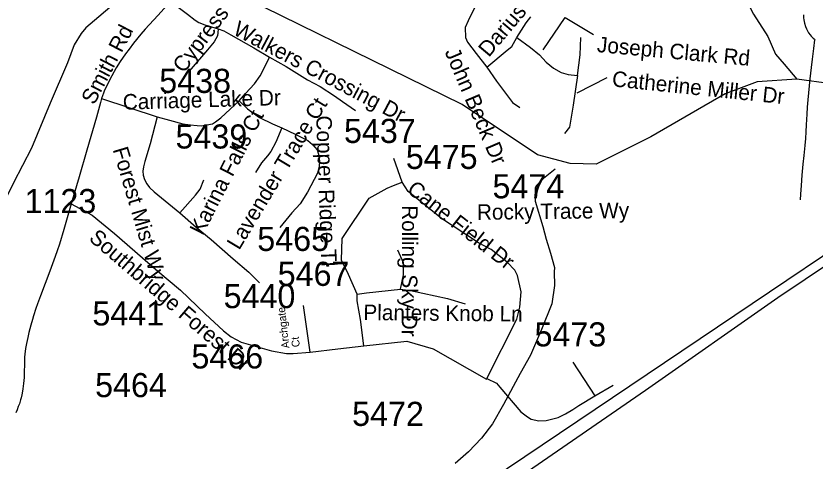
# Model space of a CAD drawing. Extents: x 1383679 to 1536984, y 460658 to 651027.
# Drawn here: x 1409147 to 1414038, y 493101 to 495826 of the extents above; entities that cross this region are included whole.
import ezdxf

# ---------------------------------------------------------------- set-up
doc = ezdxf.new("R2010")
doc.units = 0
for name, color, linetype in [('Default', 7, 'Continuous'), ('Exist Boundary Political City Limit New', 7, 'Continuous'), ('Exist Boundary Political StateLine', 7, 'Continuous'), ('Exist Hydrographic Creek Single Shore', 7, 'Continuous'), ('Exist Hydrographic Misc Water Feature', 7, 'Continuous'), ('Exist Road Non-System Secondary Historical Number Label', 7, 'Continuous'), ('Exist Road Non-System Type 51', 7, 'Continuous'), ('Exist Road Non-System Type 51 Label', 7, 'Continuous'), ('Map Preparation Boundary City Limit Buffer Line', 7, 'Continuous')]:
    doc.layers.add(name, color=color, linetype=linetype)

msp = doc.modelspace()

# ---------------------------------------------------------------- linework, layer by layer
at = {"layer": 'Default'}
msp.add_lwpolyline([(1418935.2, 497827.7), (1418342.2, 497382), (1417593.1, 496829.8), (1416984, 496372.7), (1416228.9, 495820.4), (1415794, 495503.8), (1404876.5, 488155.8)], dxfattribs=at)
at = {"layer": 'Exist Boundary Political City Limit New'}
msp.add_lwpolyline([(1418935.2, 497827.7), (1418342.2, 497382), (1417593.1, 496829.8), (1416984, 496372.7), (1416228.9, 495820.4), (1415794, 495503.8), (1404876.5, 488155.8)], dxfattribs=at)
at = {"layer": 'Exist Boundary Political StateLine'}
msp.add_lwpolyline([(1418935.3, 497827.7), (1418342.2, 497382), (1417593.1, 496829.8), (1416984, 496372.6), (1416228.9, 495820.4), (1415408.9, 495223.6), (1414915.6, 494851.9), (1414651.9, 494665.6), (1413810.5, 494099.2), (1412999.1, 493532.3), (1412191.9, 492975.2), (1411452.1, 492476.7), (1410572.2, 491891.1), (1409803.9, 491375.3), (1409059.8, 490872.9), (1408384.8, 490425), (1407598.3, 489901.6), (1406702.3, 489298.3), (1405745.5, 488656.5)], dxfattribs=at)
at = {"layer": 'Exist Hydrographic Creek Single Shore'}
for points in [[(1414136.5, 495410.6), (1413927.4, 495438.7), (1413683.6, 495422.8), (1413487.7, 495349.3), (1413033.2, 495086.4), (1412697.2, 494919.1), (1412538.2, 494922.4), (1412339.2, 494975.6), (1411878.2, 495283.6), (1410222.7, 496097.7), (1409667.2, 496246.2), (1408961.2, 496615.8), (1408830.2, 496703.8), (1408625.2, 496898.3), (1408270.2, 497105.7), (1407798.2, 497256.3), (1407726.2, 497415.3), (1407483.3, 497778), (1407278.2, 498376.2)], [(1413106.4, 496327.6), (1413175.2, 496263.8), (1413271.7, 496188), (1413441.8, 496087), (1413565.8, 495980.2), (1413616.8, 495923.4), (1413661.1, 495838), (1413748.5, 495700.9), (1413796.4, 495593.2), (1413849.2, 495530.6), (1413927.4, 495438.7)]]:
    msp.add_lwpolyline(points, dxfattribs=at)
at = {"layer": 'Exist Hydrographic Misc Water Feature'}
for points in [[(1410138.7, 496109.2), (1410045.8, 496066.7), (1409908.4, 495997.3), (1409774.9, 495924.5), (1409573.5, 495753.7), (1409544.8, 495718.2), (1409503.5, 495649.3), (1409461.3, 495540.1), (1409356.4, 495292), (1409240.9, 495016.1), (1409130.7, 494804.2), (1409080.7, 494699.3), (1409043.3, 494629.5)], [(1412448, 494887.6), (1412374.8, 494830.8), (1412329.9, 494785.7), (1412325.6, 494771.9), (1412325, 494745.6), (1412324.1, 494692.3), (1412371.1, 494537.1), (1412391.5, 494458.7), (1412417.9, 494373.7), (1412442.2, 494285.3), (1412441.6, 494259.1), (1412442.1, 494175.4), (1412425.9, 494063.3), (1412362.8, 493907), (1412295.7, 493750), (1412233.5, 493637.2), (1412131.7, 493447.2), (1412063.4, 493327.9), (1411995.6, 493239.9), (1411915.9, 493156.9), (1411834.4, 493084.7)]]:
    msp.add_lwpolyline(points, dxfattribs=at)
at = {"layer": 'Exist Road Non-System Type 51'}
for p, q in [((1409670.9, 495319.9), (1410011.8, 495207.5)), ((1411510.1, 494808.5), (1411460.3, 494953.6)), ((1412554.5, 493706.1), (1412690.8, 493500)), ((1412690.8, 493500), (1412803, 493566))]:
    msp.add_line(p, q, dxfattribs=at)
for points in [[(1412080.1, 496108.3), (1411991.5, 495957.6), (1411915.4, 495796.2), (1411896.4, 495754.7), (1411898.8, 495694.8), (1411910.7, 495664.8), (1411962.9, 495595.6), (1412029.5, 495512.6)], [(1410093, 495915.2), (1410014.9, 495828.4), (1409937.9, 495745.3), (1409911.7, 495714.9), (1409866.4, 495658.8), (1409839, 495623.7), (1409817.7, 495594.2), (1409784.5, 495547.6), (1409760.3, 495509.3), (1409733.1, 495459.6), (1409710.2, 495416), (1409697.7, 495389.7), (1409689.1, 495371.2), (1409682.2, 495353.1), (1409670.9, 495319.9)], [(1410093, 495915.2), (1410195.5, 495837.3), (1410244.1, 495801.2), (1410265.3, 495786.5), (1410303.3, 495772.5), (1410384.5, 495747.5)], [(1412212.5, 495694.8), (1412269.5, 495784.7), (1412298, 495821.6)], [(1413967.1, 495834), (1413967.8, 495814.6), (1413969.1, 495802.9), (1413973.2, 495782.8), (1413979.8, 495762.3), (1413986.1, 495746.5), (1413993.3, 495731.9), (1413998.5, 495723.5), (1414007.2, 495711.1), (1414013.9, 495703), (1414026.7, 495689.5), (1414033.6, 495683.1), (1414037.6, 495679.7)], [(1412374.3, 495618.1), (1412507.8, 495816.1), (1412681, 495712.1)], [(1410384.5, 495747.5), (1410383, 495722.4), (1410379.2, 495704.7), (1410370.9, 495687.1), (1410359.5, 495667.2), (1410318.5, 495617.8), (1410206.1, 495488.9)], [(1410384.5, 495747.5), (1410418.7, 495734.9), (1410462.7, 495711.4), (1410601.7, 495631.1), (1410698.8, 495574.4)], [(1412029.5, 495512.6), (1412153.1, 495616.3), (1412181.6, 495639.4), (1412212.5, 495694.8)], [(1412212.5, 495694.8), (1412295.6, 495632.5), (1412351.5, 495587.5), (1412391.9, 495543.7), (1412437, 495506.8), (1412484.6, 495479.1), (1412527.3, 495467.6), (1412584.4, 495460.7)], [(1412584.4, 495460.7), (1412601, 495587.5), (1412603.4, 495693.6)], [(1413948.5, 494699.5), (1413950.7, 494735.8), (1413954.1, 494787), (1413959.4, 494851.6), (1413965.5, 494918.8), (1413971.5, 494971.9), (1413977.7, 495033.8), (1413981.7, 495074.8), (1413984, 495116.5), (1413985.3, 495158.5), (1413988.8, 495224.7), (1413991.8, 495268.3), (1413995.6, 495313.1), (1414000, 495354.7), (1414008.6, 495441.5), (1414015.3, 495509.7), (1414021.9, 495562.2), (1414030.4, 495627.4), (1414037.6, 495679.7)], [(1414037.6, 495679.7), (1414039.1, 495678.5)], [(1410512.8, 495306.2), (1410552.3, 495350.4), (1410606.2, 495410.8), (1410641.1, 495458.7), (1410663.9, 495502.2), (1410698.8, 495574.4)], [(1410698.8, 495574.4), (1410799.8, 495517.6), (1410931.1, 495435.9), (1411007.8, 495394.6), (1411096.6, 495337.2), (1411146, 495303.3), (1411224.2, 495248.1)], [(1412029.5, 495512.6), (1412087.7, 495426.1), (1412185.1, 495296.9), (1412230.3, 495264.7)], [(1412584.4, 495460.7), (1412558.2, 495280.8), (1412534.5, 495144.7), (1412503.6, 495105.5)], [(1412582, 495355.7), (1412765, 495449.8)], [(1409670.9, 495319.9), (1409663.6, 495296.2), (1409638.5, 495206.5), (1409581.2, 495003.8), (1409533.1, 494840.1), (1409485, 494676.4)], [(1410011.8, 495207.5), (1410085.4, 495188.4), (1410167.4, 495164.8), (1410213.7, 495159.7), (1410255.5, 495154.5), (1410281.3, 495153), (1410315.4, 495159.7), (1410348.8, 495166.3), (1410367.1, 495177.3), (1410399.7, 495201.6), (1410512.8, 495306.2)], [(1410512.8, 495306.2), (1410562.9, 495257.6), (1410637.3, 495204.6), (1410716.3, 495166.3), (1410774, 495141.3)], [(1410011.8, 495207.5), (1409968.5, 495043.3), (1409935.1, 494935.7), (1409927.5, 494903.3), (1409923.7, 494876.8), (1409924.5, 494851), (1409933.6, 494825.3), (1409947.2, 494797.3), (1409963.9, 494775.9), (1409992.8, 494749.4), (1410149.2, 494619.7)], [(1410774, 495141.3), (1410737.5, 495054.3), (1410707.2, 494995.4), (1410685.9, 494968.9), (1410649.5, 494927.6), (1410613.4, 494867.5)], [(1410774, 495141.3), (1410856, 495102.9), (1410933.4, 495063.2), (1410961.4, 495040), (1410989.6, 495007.2), (1410998.7, 494980.7), (1411004.8, 494936.5), (1411003.3, 494905.5), (1410992.6, 494864.3), (1410930.4, 494746.4), (1410886.3, 494675.7), (1410834.7, 494619.7), (1410760.8, 494529.9)], [(1410149.2, 494619.7), (1410245.6, 494729.5), (1410274.4, 494765.6), (1410296.5, 494822.3)], [(1411234.5, 494122.5), (1411181.5, 494242.1), (1411139.2, 494331.8), (1411144.1, 494463.8), (1411308.4, 494710.4), (1411419.5, 494772.3), (1411457.7, 494787.6), (1411510.1, 494808.5)], [(1412026.6, 493602.6), (1412212.4, 493969.8), (1412230.5, 494042.4), (1412239.6, 494137.6), (1412216.9, 494237.3), (1412199.3, 494269.5), (1412153.5, 494318.9), (1412054.8, 494396.4), (1411977.7, 494437.2), (1411751.4, 494585.9), (1411547.3, 494750.3), (1411510.1, 494808.5)], [(1409485, 494676.4), (1409439.8, 494518.4), (1409412.4, 494428.2), (1409399.7, 494388.6), (1409387.3, 494353.2), (1409353.4, 494263.8), (1409296.4, 494112.1), (1409278.7, 494063), (1409268.3, 494034.3), (1409253.4, 493990.1), (1409246.8, 493967.9), (1409237.3, 493933.4), (1409225.6, 493888.1), (1409218.6, 493857.2), (1409211.5, 493820.8), (1409205.6, 493789.7), (1409200.8, 493754.6), (1409199.1, 493735.8), (1409198, 493713.6), (1409198, 493698.1), (1409197.1, 493639.9), (1409196.1, 493612.5), (1409192.6, 493576.1), (1409188.4, 493543.2), (1409183.5, 493517.1), (1409181.6, 493506.5), (1409177.9, 493488.6), (1409174.9, 493476.2), (1409167.2, 493451.4), (1409160.6, 493434.1), (1409152.9, 493415), (1409144.8, 493395.9)], [(1409485, 494676.4), (1409612.6, 494606.3), (1409750.5, 494493.3), (1410014.3, 494262.7), (1410154.5, 494147.3), (1410304.2, 494002.1), (1410415.9, 493898.3), (1410463.4, 493861.4), (1410525.2, 493829.1), (1410710.6, 493776.1), (1410803.2, 493759.9), (1410843.6, 493759.9), (1410947.3, 493767)], [(1410149.2, 494619.7), (1410250.1, 494532.8), (1410341.2, 494457), (1410475.6, 494338.4), (1410572.8, 494256.6), (1410637.3, 494191.8)], [(1411500.7, 494153.2), (1411519.7, 494240.3), (1411519.7, 494315), (1411484.9, 494392.2)], [(1411234.5, 494122.5), (1411291.3, 494131.2), (1411500.7, 494153.2)], [(1411500.7, 494153.2), (1411562.1, 494145.6), (1411788.5, 494095.8), (1411895.5, 494063.4)], [(1411276.1, 493806), (1411255.7, 493966.9), (1411234.6, 494081.6), (1411234.5, 494122.5)], [(1410947.3, 493767), (1410907.5, 494053.5)], [(1411276.1, 493806), (1411538.5, 493835.6), (1411700.4, 493788.4), (1412026.6, 493602.6)], [(1410947.3, 493767), (1411116.9, 493787.6), (1411276.1, 493806)], [(1412028.4, 493607), (1412087.5, 493576.7), (1412109.1, 493552.8), (1412237.1, 493402.3), (1412278.4, 493371.2), (1412299.4, 493357.6), (1412346.4, 493346), (1412391.9, 493348.2), (1412465.1, 493367.3), (1412510.9, 493390), (1412555.6, 493417.3), (1412591.1, 493441.1), (1412690.8, 493500)]]:
    msp.add_lwpolyline(points, dxfattribs=at)
at = {"layer": 'Map Preparation Boundary City Limit Buffer Line'}
msp.add_lwpolyline([(1418935.2, 497827.7), (1418342.2, 497382), (1417593.1, 496829.8), (1416984, 496372.7), (1416228.9, 495820.4), (1415794, 495503.8), (1404876.5, 488155.8)], dxfattribs=at)
msp.add_lwpolyline([(1418935.2, 497827.7), (1418342.2, 497382), (1417593.1, 496829.8), (1416984, 496372.7), (1416228.9, 495820.4), (1415794, 495503.8), (1404876.5, 488155.8)], dxfattribs=at)

# ---------------------------------------------------------------- texts
at = {"layer": 'Exist Road Non-System Secondary Historical Number Label'}
for s, p in [('5438', (1410023.6, 495354.9)), ('5437', (1411154.5, 495048.4)), ('5439', (1410123.3, 495014.4)), ('5475', (1411532.9, 494889.3)), ('5474', (1412063.5, 494709.5)), ('1123', (1409199, 494618.8)), ('5465', (1410623.6, 494387.2)), ('5467', (1410748.6, 494173.3)), ('5440', (1410417.7, 494037)), ('5441', (1409614.4, 493930.9)), ('5473', (1412320.7, 493802.6)), ('5466', (1410220.5, 493667.4)), ('5464', (1409631, 493491.9)), ('5472', (1411204.2, 493315.8))]:
    msp.add_text(s, height=147.64, dxfattribs=at).set_placement(p)
at = {"layer": 'Exist Road Non-System Type 51 Label'}
for s, height, rotation, p in [('Cypress Park Ln', 95, 52.8637, (1410173.6, 495471)), ('Darius Kay Ct', 95, 49.9159, (1412040.8, 495569.2)), ('Smith Rd', 95, 62.3858, (1409625.3, 495277)), ('Walkers Crossing Dr', 95, 332.1343, (1410468.7, 495716.6)), ('Joseph Clark Rd', 95, 354.7879, (1412700.1, 495605.8)), ('John Beck Dr', 95, 293.1258, (1411769.2, 495606.5)), ('Catherine Miller Dr', 95, 354.0466, (1412792, 495395.9)), ('Carriage Lake Dr', 95, 1.6911, (1409801.7, 495252)), ('Lavender Trace Ct', 95, 58.8877, (1410512.5, 494387.8)), ('Karina Falls Ct', 95, 63.081, (1410289.6, 494477.6)), ('Copper Ridge Tl', 95, 272.0087, (1410983.8, 495215.3)), ('Forest Mist Wy', 95, 286.5338, (1409737.9, 495008.8)), ('Cane Field Dr', 95, 321.9176, (1411533.7, 494751.1)), ('Rolling Sky Dr', 95, 269.842, (1411510, 494667.5)), ('Rocky Trace Wy', 95, 0.7033, (1411968.6, 494577.5)), ('Southbridge Forest Dr', 95, 319.3734, (1409587.2, 494456.7)), ('Planters Knob Ln', 95, 359.4288, (1411272.9, 493964.3)), ('Archgate', 47.5, 96.5114, (1410821, 493793.3)), ('Ct', 47.5, 96.5114, (1410884.5, 493800.6))]:
    msp.add_text(s, height=height, rotation=rotation, dxfattribs=at).set_placement(p)

doc.saveas('drawing.dxf')
